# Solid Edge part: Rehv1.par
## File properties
Last saved by: KULL
Revision: 77
Accuracy: 0,990
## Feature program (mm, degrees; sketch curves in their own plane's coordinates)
sketch for "unnamed RevolvedProtrusion 1" plane through (0, 0, 0) normal (0, -1, 0) x-axis (1, 0, 0)
  line (-37.8615, 50.482) -> (-20, 50.482)
  line (-2.1385, 50.482) -> (-20, 50.482)
  arc centre (-2.1385, 47.1178) radius 3.3642 from (1.2257, 47.1178) to (-2.1385, 50.482) ccw
  line (1.2257, 43.1591) -> (1.2257, 47.1178)
  line (-0.7133, 43.6493) -> (1.2257, 43.1591)
  line (-1.2519, 41.5194) -> (-0.7133, 43.6493)
  arc centre (-2.803, 41.9116) radius 1.6 from (-1.2519, 41.5194) to (-2.803, 40.3116) cw
  line (-2.803, 40.3116) -> (-2.803, 41.3116)
  arc centre (-2.803, 41.9116) radius 0.6 from (-2.803, 41.3116) to (-2.2213, 41.7645) ccw
  line (-2.2213, 41.7645) -> (-1.4377, 44.864)
  line (-1.4377, 44.864) -> (0.2257, 44.4434)
  line (0.2257, 44.4434) -> (0.2257, 47.1178)
  arc centre (-2.1385, 47.1178) radius 2.3642 from (0.2257, 47.1178) to (-2.1385, 49.482) ccw
  line (-2.1385, 49.482) -> (-20, 49.482)
  line (-37.8615, 49.482) -> (-20, 49.482)
  arc centre (-37.8615, 47.1178) radius 2.3642 from (-40.2257, 47.1178) to (-37.8615, 49.482) cw
  line (-40.2257, 44.4434) -> (-40.2257, 47.1178)
  line (-38.5623, 44.864) -> (-40.2257, 44.4434)
  line (-37.7787, 41.7645) -> (-38.5623, 44.864)
  arc centre (-37.197, 41.9116) radius 0.6 from (-37.197, 41.3116) to (-37.7787, 41.7645) cw
  line (-37.197, 40.3116) -> (-37.197, 41.3116)
  arc centre (-37.197, 41.9116) radius 1.6 from (-38.7481, 41.5194) to (-37.197, 40.3116) ccw
  line (-38.7481, 41.5194) -> (-39.2867, 43.6493)
  line (-39.2867, 43.6493) -> (-41.2257, 43.1591)
  line (-41.2257, 43.1591) -> (-41.2257, 47.1178)
  arc centre (-37.8615, 47.1178) radius 3.3642 from (-41.2257, 47.1178) to (-37.8615, 50.482) cw
revolve "unnamed RevolvedProtrusion 1" add finite 360 deg
fillet "unnamed Round 1"
normal to face cutouts "Normal_Cutout_308"  Thickness = 0.4 mm
pattern "unnamed Pattern 1" of "Normal_Cutout_308"
pattern "unnamed Pattern 2"
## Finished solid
Body 1: solid body, 650 faces, 1688 edges, 1040 vertices.
  Faces by surface: spline 520, torus 62, cylinder 54, cone 8, plane 6
  Edges by curve: intersection 1040, line 390, curve on surface 130, circle 128
Bounding box of the edges (mm; curved faces can reach further): 42.451 x 100.967 x 100.966, from (-41.2257, -50.4835, -50.483) to (1.2257, 50.4835, 50.483).
Cylindrical faces by radius (mm): R49.482 x1, R50.082 x52, R50.482 x1
Conical faces (half-angle, radius in mm at the cone's reference point): 14.1898 deg R43.1591 x1, 14.1898 deg R43.6493 x1, 14.1898 deg R44.4434 x1, 14.1898 deg R44.864 x1, 75.8102 deg R41.5194 x1, 75.8102 deg R41.7645 x1, 75.8102 deg R43.6493 x1, 75.8102 deg R44.864 x1
Toroidal faces (ring radius, tube radius in mm): R41.9116 r0.6 x2, R41.9116 r1.6 x2, R43.4159 r0.2 x2, R47.1178 r2.3642 x2, R47.1178 r2.9642 x52, R47.1178 r3.3642 x2
Planar faces by outward normal: +x 3, -x 3
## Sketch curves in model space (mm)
line (-49.3748, 0, 0) -> (16.874, 0, 0)
line (-2.1385, -49.482, 0) -> (-9.1087, -49.482, 0)
circle centre (-35.0729, -50.9512, 0) radius 1.2289
circle centre (-4.9273, -50.9512, 0) radius 1.2289
circle centre (-20.0001, -50.9512, 0) radius 1.2797
arc centre (-0.4159, -8.7375, 54.1018) radius 0.1325 from (-0.4334, -8.8688, 54.1018) through (-0.2859, -8.7631, 54.1018) to (-0.3823, -8.6094, 54.1018)
spline (-13.9117, -0.5447, 54.1018) -> (-9.3205, -5.2643, 54.1018) -> (-0.3823, -8.6094, 54.1018)
arc centre (-13.5217, -0.3349, 54.1018) radius 0.4428 from (-13.2494, 0.0142, 54.1018) through (-13.8268, -0.014, 54.1018) to (-13.9117, -0.5447, 54.1018)
spline (-3.8251, -4.0874, 54.1018) -> (-9.662, -2.1312, 54.1018) -> (-13.2494, 0.0142, 54.1018)
arc centre (-3.7765, -3.8787, 54.1018) radius 0.2142 from (-3.6857, -3.6847, 54.1018) through (-3.5786, -3.9608, 54.1018) to (-3.8251, -4.0874, 54.1018)
spline (-18.0817, 8.9067, 54.1018) -> (-12.9741, 2.4271, 54.1018) -> (-3.6857, -3.6847, 54.1018)
arc centre (-18.3642, 8.7585, 54.1018) radius 0.319 from (-18.6815, 8.7262, 54.1018) through (-18.4471, 9.0665, 54.1018) to (-18.0817, 8.9067, 54.1018)
spline (-18.6815, 8.7262, 54.1018) -> (-14.1902, -3.2855, 54.1018) -> (-0.4334, -8.8688, 54.1018)
arc centre (-39.5841, -8.7375, 54.1018) radius 0.1325 from (-39.5666, -8.8688, 54.1018) through (-39.7141, -8.7631, 54.1018) to (-39.6177, -8.6094, 54.1018)
spline (-26.0883, -0.5447, 54.1018) -> (-30.6795, -5.2643, 54.1018) -> (-39.6177, -8.6094, 54.1018)
arc centre (-26.4783, -0.3349, 54.1018) radius 0.4428 from (-26.7506, 0.0142, 54.1018) through (-26.1732, -0.014, 54.1018) to (-26.0883, -0.5447, 54.1018)
spline (-36.1749, -4.0874, 54.1018) -> (-30.338, -2.1312, 54.1018) -> (-26.7506, 0.0142, 54.1018)
arc centre (-36.2235, -3.8787, 54.1018) radius 0.2142 from (-36.3143, -3.6847, 54.1018) through (-36.4214, -3.9608, 54.1018) to (-36.1749, -4.0874, 54.1018)
spline (-21.9183, 8.9067, 54.1018) -> (-27.0259, 2.4271, 54.1018) -> (-36.3143, -3.6847, 54.1018)
arc centre (-21.6358, 8.7585, 54.1018) radius 0.319 from (-21.3185, 8.7262, 54.1018) through (-21.5529, 9.0665, 54.1018) to (-21.9183, 8.9067, 54.1018)
spline (-21.3185, 8.7262, 54.1018) -> (-25.8098, -3.2855, 54.1018) -> (-39.5666, -8.8688, 54.1018)
line (-46.7602, 0, 0) -> (13.5194, 0, 0)
line (-39.2867, 0, 43.6493) -> (-41.2257, 0, 43.1591)
line (-41.2257, 0, 43.1591) -> (-41.2257, 0, 47.1178)
arc centre (-37.8615, 0, 47.1178) radius 3.3642 from (-41.2257, 0, 47.1178) through (-40.1701, 0, 49.5649) to (-37.8615, 0, 50.482)
line (-37.8615, 0, 50.482) -> (-20, 0, 50.482)
line (-2.1385, 0, 50.482) -> (-20, 0, 50.482)
arc centre (-2.1385, 0, 47.1178) radius 3.3642 from (1.2257, 0, 47.1178) through (0.1701, 0, 49.5649) to (-2.1385, 0, 50.482)
line (1.2257, 0, 43.1591) -> (1.2257, 0, 47.1178)
line (-0.7133, 0, 43.6493) -> (1.2257, 0, 43.1591)
line (-1.2519, 0, 41.5194) -> (-0.7133, 0, 43.6493)
arc centre (-2.803, 0, 41.9116) radius 1.6 from (-1.2519, 0, 41.5194) through (-1.8568, 0, 40.6214) to (-2.803, 0, 40.3116)
line (-2.803, 0, 40.3116) -> (-2.803, 0, 41.3116)
arc centre (-2.803, 0, 41.9116) radius 0.6 from (-2.803, 0, 41.3116) through (-2.421, 0, 41.449) to (-2.2213, 0, 41.7645)
line (-2.2213, 0, 41.7645) -> (-1.4377, 0, 44.864)
line (-1.4377, 0, 44.864) -> (0.2257, 0, 44.4434)
line (0.2257, 0, 44.4434) -> (0.2257, 0, 47.1178)
arc centre (-2.1385, 0, 47.1178) radius 2.3642 from (0.2257, 0, 47.1178) through (-0.5161, 0, 48.8375) to (-2.1385, 0, 49.482)
line (-2.1385, 0, 49.482) -> (-20, 0, 49.482)
line (-37.8615, 0, 49.482) -> (-20, 0, 49.482)
arc centre (-37.8615, 0, 47.1178) radius 2.3642 from (-40.2257, 0, 47.1178) through (-39.4839, 0, 48.8375) to (-37.8615, 0, 49.482)
line (-40.2257, 0, 44.4434) -> (-40.2257, 0, 47.1178)
line (-38.5623, 0, 44.864) -> (-40.2257, 0, 44.4434)
line (-37.7787, 0, 41.7645) -> (-38.5623, 0, 44.864)
arc centre (-37.197, 0, 41.9116) radius 0.6 from (-37.197, 0, 41.3116) through (-37.579, 0, 41.449) to (-37.7787, 0, 41.7645)
line (-37.197, 0, 40.3116) -> (-37.197, 0, 41.3116)
arc centre (-37.197, 0, 41.9116) radius 1.6 from (-38.7481, 0, 41.5194) through (-38.1432, 0, 40.6214) to (-37.197, 0, 40.3116)
line (-38.7481, 0, 41.5194) -> (-39.2867, 0, 43.6493)
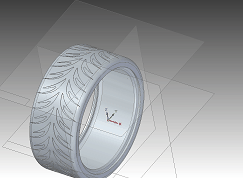
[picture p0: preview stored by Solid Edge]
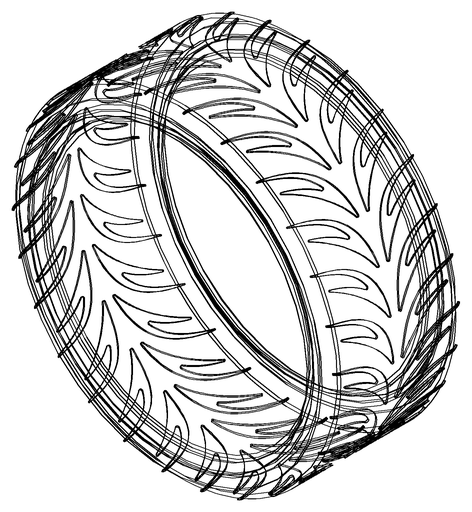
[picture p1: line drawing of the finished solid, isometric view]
